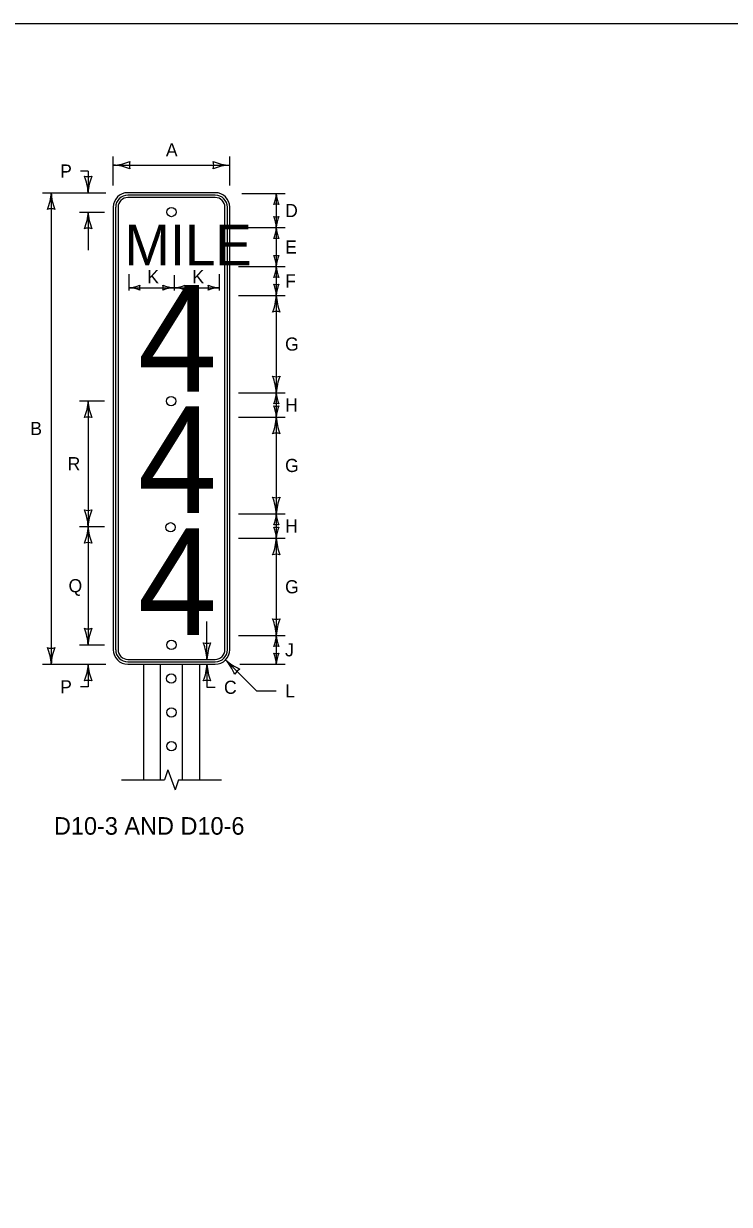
# Model space of a CAD drawing. Extents: x 49991.4 to 50021, y 49987.6 to 50011.4.
# Drawn here: x 50008.65 to 50011.87, y 49993.61 to 49999 of the extents above; entities that cross this region are included whole.
import ezdxf

# ---------------------------------------------------------------- set-up
doc = ezdxf.new("R2010")
doc.units = 0
for name, color, linetype in [('Level 1', 7, 'Continuous'), ('Level 2', 7, 'Continuous'), ('Level 3', 7, 'Continuous'), ('Level 6', 7, 'Continuous')]:
    doc.layers.add(name, color=color, linetype=linetype)

msp = doc.modelspace()

# ---------------------------------------------------------------- linework, layer by layer
at = {"layer": 'Level 1'}
for p, q in [((50009.5245, 49998.2278), (50009.1261, 49998.2278)), ((50009.5246, 49998.2167), (50009.1261, 49998.2167)), ((50009.5246, 49998.2057), (50009.1261, 49998.2057)), ((50009.0597, 49998.1614), (50009.0597, 49996.1429)), ((50009.0707, 49998.1614), (50009.0707, 49996.143)), ((50009.0818, 49998.1615), (50009.0818, 49996.1429)), ((50009.5688, 49996.1429), (50009.5688, 49998.1615)), ((50009.5799, 49996.143), (50009.5799, 49998.1614)), ((50009.5909, 49996.1429), (50009.5909, 49998.1614)), ((50009.1261, 49996.0986), (50009.5246, 49996.0986)), ((50009.1261, 49996.0876), (50009.5246, 49996.0876)), ((50009.1261, 49996.0765), (50009.5245, 49996.0765)), ((50009.1975, 49996.0765), (50009.1975, 49995.5489)), ((50009.2732, 49996.0765), (50009.2732, 49995.5489)), ((50009.3737, 49996.0765), (50009.3737, 49995.5489)), ((50009.4529, 49996.0765), (50009.4529, 49995.5489))]:
    msp.add_line(p, q, dxfattribs=at)
msp.add_lwpolyline([(49999.3835, 49998.9992), (50016.7501, 49998.9992), (50016.7501, 49987.7988), (49999.3835, 49987.7988)], close=True, dxfattribs=at)
for centre in [(50009.3252, 49998.1397), (50009.3232, 49997.2773), (50009.321, 49996.7012), (50009.3252, 49996.1646), (50009.324, 49996.0109), (50009.3252, 49995.8567), (50009.3252, 49995.7028)]:
    msp.add_circle(centre, 0.0213, dxfattribs=at)
for centre, radius, start, end in [((50009.1261, 49998.1614), 0.0664, 90, 180), ((50009.1261, 49998.1614), 0.0553, 90, 180), ((50009.1261, 49998.1615), 0.0443, 90, 180), ((50009.5245, 49998.1614), 0.0664, 0, 90), ((50009.5246, 49998.1614), 0.0553, 0, 90), ((50009.5246, 49998.1615), 0.0443, 0, 90), ((50009.1261, 49996.1429), 0.0664, 180, 270), ((50009.1261, 49996.143), 0.0553, 180, 270), ((50009.1261, 49996.1429), 0.0443, 180, 270), ((50009.5245, 49996.1429), 0.0664, 270, 360), ((50009.5246, 49996.143), 0.0553, 270, 360), ((50009.5246, 49996.1429), 0.0443, 270, 360)]:
    msp.add_arc(centre, radius, start, end, dxfattribs=at)
at = {"layer": 'Level 3'}
for p, q in [((50009.0597, 49998.2614), (50009.0597, 49998.3933)), ((50009.0597, 49998.3533), (50009.5909, 49998.3533)), ((50009.5909, 49998.2614), (50009.5909, 49998.3933)), ((50008.9453, 49998.3265), (50008.9111, 49998.3265)), ((50008.9453, 49998.3265), (50008.9453, 49998.2277)), ((50008.7369, 49998.2277), (50009.0261, 49998.2277)), ((50008.7769, 49998.2277), (50008.7769, 49996.0765)), ((50009.6464, 49998.2241), (50009.843, 49998.2241)), ((50009.803, 49998.2241), (50009.803, 49998.0689)), ((50008.9053, 49998.1397), (50009.0197, 49998.1397)), ((50008.9453, 49998.1397), (50008.9453, 49997.9663)), ((50009.6309, 49998.0689), (50009.843, 49998.0689)), ((50009.803, 49998.0689), (50009.803, 49997.8912)), ((50009.6309, 49997.8912), (50009.843, 49997.8912)), ((50009.803, 49997.8912), (50009.803, 49997.7593)), ((50009.1307, 49997.8558), (50009.1307, 49997.782)), ((50009.1307, 49997.8539), (50009.1307, 49997.782)), ((50009.1307, 49997.8521), (50009.1307, 49997.782)), ((50009.3368, 49997.8521), (50009.3368, 49997.782)), ((50009.5428, 49997.8558), (50009.5428, 49997.782)), ((50009.5428, 49997.8539), (50009.5428, 49997.782)), ((50009.5428, 49997.8521), (50009.5428, 49997.782)), ((50009.1307, 49997.7945), (50009.3538, 49997.7945)), ((50009.1307, 49997.7945), (50009.3538, 49997.7945)), ((50009.1307, 49997.7945), (50009.3538, 49997.7945)), ((50009.3538, 49997.7945), (50009.5428, 49997.7945)), ((50009.3538, 49997.7945), (50009.5428, 49997.7945)), ((50009.3538, 49997.7945), (50009.5428, 49997.7945)), ((50009.6309, 49997.7593), (50009.843, 49997.7593)), ((50009.803, 49997.7593), (50009.803, 49997.315)), ((50008.9053, 49997.2779), (50009.0197, 49997.2779)), ((50008.9453, 49997.2779), (50008.9453, 49996.705)), ((50009.6309, 49997.315), (50009.843, 49997.315)), ((50009.803, 49997.315), (50009.803, 49997.2042)), ((50009.6309, 49997.2042), (50009.843, 49997.2042)), ((50009.803, 49997.2042), (50009.803, 49996.7626)), ((50009.6309, 49996.7626), (50009.843, 49996.7626)), ((50009.803, 49996.7626), (50009.803, 49996.6518)), ((50008.9053, 49996.705), (50009.0197, 49996.705)), ((50008.9453, 49996.705), (50008.9453, 49996.1646)), ((50009.6309, 49996.6518), (50009.843, 49996.6518)), ((50009.803, 49996.6518), (50009.803, 49996.2082)), ((50009.4869, 49996.0986), (50009.4867, 49996.2721)), ((50009.6309, 49996.2082), (50009.843, 49996.2082)), ((50009.6309, 49996.2082), (50009.843, 49996.2082)), ((50009.803, 49996.2082), (50009.803, 49996.0765)), ((50008.9053, 49996.1646), (50009.0197, 49996.1646)), ((50009.5718, 49996.0963), (50009.7131, 49995.955)), ((50008.7369, 49996.0765), (50009.0261, 49996.0765)), ((50008.9453, 49996.0765), (50008.9453, 49995.9736)), ((50009.4869, 49996.0765), (50009.4869, 49995.9715)), ((50009.637, 49996.0765), (50009.843, 49996.0765)), ((50008.9453, 49995.9736), (50008.9111, 49995.9736)), ((50009.4869, 49995.9715), (50009.5245, 49995.9715)), ((50009.7131, 49995.955), (50009.803, 49995.955))]:
    msp.add_line(p, q, dxfattribs=at)
for centre, radius, start, end in [((50009.0482, 49998.586), 0.233, 272.8273, 292.0772), ((50009.0506, 49998.1312), 0.2223, 67.456, 87.6395), ((50009.1879, 49998.3533), 0.0548, 162.1388, 197.8612), ((50009.6001, 49998.5755), 0.2223, 247.456, 267.6395), ((50009.4627, 49998.3533), 0.0548, 342.1388, 17.8612), ((50009.6024, 49998.1206), 0.233, 92.8273, 112.0772), ((50008.9453, 49998.3559), 0.0548, 252.1388, 287.8612), ((50008.7126, 49998.2162), 0.233, 2.8273, 22.0772), ((50009.1675, 49998.2186), 0.2223, 157.456, 177.6395), ((50008.5548, 49998.2369), 0.2223, 337.456, 357.6395), ((50009.0096, 49998.2392), 0.233, 182.8273, 202.0772), ((50009.6549, 49998.2302), 0.1482, 337.456, 357.6395), ((50009.9582, 49998.2318), 0.1553, 182.8273, 202.0772), ((50008.7769, 49998.0995), 0.0548, 72.1388, 107.8612), ((50008.7232, 49998.1489), 0.2223, 337.456, 357.6395), ((50009.178, 49998.1512), 0.233, 182.8273, 202.0772), ((50009.803, 49998.1387), 0.0365, 72.1388, 107.8612), ((50009.803, 49998.1544), 0.0365, 252.1388, 287.8612), ((50009.6479, 49998.0613), 0.1553, 2.8273, 22.0772), ((50009.9511, 49998.0628), 0.1482, 157.456, 177.6395), ((50008.9453, 49998.0115), 0.0548, 72.1388, 107.8612), ((50009.6549, 49998.075), 0.1482, 337.456, 357.6395), ((50009.9582, 49998.0766), 0.1553, 182.8273, 202.0772), ((50009.803, 49997.9835), 0.0365, 72.1388, 107.8612), ((50009.803, 49997.9767), 0.0365, 252.1388, 287.8612), ((50009.6479, 49997.8836), 0.1553, 2.8273, 22.0772), ((50009.9511, 49997.8851), 0.1482, 157.456, 177.6395), ((50009.6549, 49997.8973), 0.1482, 337.456, 357.6395), ((50009.9582, 49997.8989), 0.1553, 182.8273, 202.0772), ((50009.803, 49997.8058), 0.0365, 72.1388, 107.8612), ((50009.1231, 49997.9497), 0.1553, 272.8273, 292.0772), ((50009.1231, 49997.9497), 0.1553, 272.8273, 292.0772), ((50009.1231, 49997.9497), 0.1553, 272.8273, 292.0772), ((50009.1246, 49997.6464), 0.1482, 67.456, 87.6395), ((50009.1246, 49997.6464), 0.1482, 67.456, 87.6395), ((50009.1246, 49997.6464), 0.1482, 67.456, 87.6395), ((50009.2162, 49997.7945), 0.0365, 162.1388, 197.8612), ((50009.2162, 49997.7945), 0.0365, 162.1388, 197.8612), ((50009.2162, 49997.7945), 0.0365, 162.1388, 197.8612), ((50009.3429, 49997.9426), 0.1482, 247.456, 267.6395), ((50009.2513, 49997.7945), 0.0365, 342.1388, 17.8612), ((50009.3444, 49997.6394), 0.1553, 92.8273, 112.0772), ((50009.3291, 49997.9497), 0.1553, 272.8273, 292.0772), ((50009.3307, 49997.6464), 0.1482, 67.456, 87.6395), ((50009.4223, 49997.7945), 0.0365, 162.1388, 197.8612), ((50009.5489, 49997.9426), 0.1482, 247.456, 267.6395), ((50009.4573, 49997.7945), 0.0365, 342.1388, 17.8612), ((50009.5489, 49997.9426), 0.1482, 247.456, 267.6395), ((50009.4573, 49997.7945), 0.0365, 342.1388, 17.8612), ((50009.5489, 49997.9426), 0.1482, 247.456, 267.6395), ((50009.4573, 49997.7945), 0.0365, 342.1388, 17.8612), ((50009.5505, 49997.6394), 0.1553, 92.8273, 112.0772), ((50009.5505, 49997.6394), 0.1553, 92.8273, 112.0772), ((50009.5505, 49997.6394), 0.1553, 92.8273, 112.0772), ((50009.5809, 49997.7685), 0.2223, 337.456, 357.6395), ((50009.803, 49997.8448), 0.0365, 252.1388, 287.8612), ((50009.6479, 49997.7517), 0.1553, 2.8273, 22.0772), ((50009.9511, 49997.7532), 0.1482, 157.456, 177.6395), ((50010.0357, 49997.7708), 0.233, 182.8273, 202.0772), ((50009.803, 49997.6311), 0.0548, 72.1388, 107.8612), ((50009.803, 49997.4432), 0.0548, 252.1388, 287.8612), ((50009.5703, 49997.3035), 0.233, 2.8273, 22.0772), ((50010.0252, 49997.3059), 0.2223, 157.456, 177.6395), ((50008.7232, 49997.2871), 0.2223, 337.456, 357.6395), ((50009.178, 49997.2894), 0.233, 182.8273, 202.0772), ((50009.6549, 49997.3211), 0.1482, 337.456, 357.6395), ((50009.9582, 49997.3227), 0.1553, 182.8273, 202.0772), ((50009.803, 49997.2296), 0.0365, 72.1388, 107.8612), ((50009.803, 49997.2897), 0.0365, 252.1388, 287.8612), ((50009.6479, 49997.1966), 0.1553, 2.8273, 22.0772), ((50009.9511, 49997.1981), 0.1482, 157.456, 177.6395), ((50008.9453, 49997.1497), 0.0548, 72.1388, 107.8612), ((50009.5809, 49997.2134), 0.2223, 337.456, 357.6395), ((50010.0357, 49997.2157), 0.233, 182.8273, 202.0772), ((50009.803, 49997.076), 0.0548, 72.1388, 107.8612), ((50009.803, 49996.8908), 0.0548, 252.1388, 287.8612), ((50009.5703, 49996.7511), 0.233, 2.8273, 22.0772), ((50010.0252, 49996.7535), 0.2223, 157.456, 177.6395), ((50008.9453, 49996.8332), 0.0548, 252.1388, 287.8612), ((50008.7126, 49996.6935), 0.233, 2.8273, 22.0772), ((50009.1675, 49996.6959), 0.2223, 157.456, 177.6395), ((50009.6549, 49996.7687), 0.1482, 337.456, 357.6395), ((50009.9582, 49996.7703), 0.1553, 182.8273, 202.0772), ((50008.7232, 49996.7142), 0.2223, 337.456, 357.6395), ((50009.178, 49996.7165), 0.233, 182.8273, 202.0772), ((50009.803, 49996.6772), 0.0365, 72.1388, 107.8612), ((50009.803, 49996.7373), 0.0365, 252.1388, 287.8612), ((50009.6479, 49996.6442), 0.1553, 2.8273, 22.0772), ((50009.9511, 49996.6457), 0.1482, 157.456, 177.6395), ((50008.9453, 49996.5768), 0.0548, 72.1388, 107.8612), ((50009.5809, 49996.661), 0.2223, 337.456, 357.6395), ((50010.0357, 49996.6633), 0.233, 182.8273, 202.0772), ((50009.803, 49996.5236), 0.0548, 72.1388, 107.8612), ((50009.803, 49996.3364), 0.0548, 252.1388, 287.8612), ((50009.5703, 49996.1967), 0.233, 2.8273, 22.0772), ((50010.0252, 49996.1991), 0.2223, 157.456, 177.6395), ((50008.9453, 49996.2928), 0.0548, 252.1388, 287.8612), ((50008.7126, 49996.1531), 0.233, 2.8273, 22.0772), ((50009.1675, 49996.1555), 0.2223, 157.456, 177.6395), ((50009.6549, 49996.2143), 0.1482, 337.456, 357.6395), ((50009.9582, 49996.2159), 0.1553, 182.8273, 202.0772), ((50008.7769, 49996.2047), 0.0548, 252.1388, 287.8612), ((50008.5442, 49996.065), 0.233, 2.8273, 22.0772), ((50008.9991, 49996.0674), 0.2223, 157.456, 177.6395), ((50009.4869, 49996.2268), 0.0548, 252.1388, 287.8612), ((50009.2542, 49996.0871), 0.233, 2.8273, 22.0772), ((50009.7091, 49996.0895), 0.2223, 157.456, 177.6395), ((50009.803, 49996.1228), 0.0365, 72.1388, 107.8612), ((50009.4083, 49995.9457), 0.2223, 22.456, 42.6395), ((50009.7282, 49996.269), 0.233, 227.8273, 247.0772), ((50009.803, 49996.162), 0.0365, 252.1388, 287.8612), ((50009.6479, 49996.0689), 0.1553, 2.8273, 22.0772), ((50009.9511, 49996.0704), 0.1482, 157.456, 177.6395), ((50008.7232, 49996.0857), 0.2223, 337.456, 357.6395), ((50009.178, 49996.088), 0.233, 182.8273, 202.0772), ((50009.2648, 49996.0857), 0.2223, 337.456, 357.6395), ((50009.7196, 49996.088), 0.233, 182.8273, 202.0772), ((50009.6625, 49996.0057), 0.0548, 117.1388, 152.8612), ((50008.9453, 49995.9483), 0.0548, 72.1388, 107.8612), ((50009.4869, 49995.9483), 0.0548, 72.1388, 107.8612)]:
    msp.add_arc(centre, radius, start, end, dxfattribs=at)
at = {"layer": 'Level 6'}
for p, q in [((50009.0975, 49995.5489), (50009.2928, 49995.5489)), ((50009.309, 49995.5946), (50009.2928, 49995.5489)), ((50009.309, 49995.5946), (50009.3252, 49995.5489)), ((50009.3252, 49995.5489), (50009.3414, 49995.5032)), ((50009.3576, 49995.5489), (50009.3414, 49995.5032)), ((50009.3576, 49995.5489), (50009.5529, 49995.5489))]:
    msp.add_line(p, q, dxfattribs=at)

# ---------------------------------------------------------------- texts
at = {"layer": 'Level 1'}
for s, height, p in [('MILE', 0.1859, (50009.1107, 49997.8958)), ('4', 0.4869, (50009.171, 49997.3203)), ('4', 0.4869, (50009.171, 49996.7669)), ('4', 0.4869, (50009.171, 49996.2093))]:
    msp.add_text(s, height=height, dxfattribs=at).set_placement(p)
at = {"layer": 'Level 2'}
for s, height, p in [('A', 0.06, (50009.2996, 49998.3933)), ('P', 0.06, (50008.8175, 49998.2965)), ('D', 0.06, (50009.843, 49998.1165)), ('E', 0.06, (50009.843, 49997.95)), ('K', 0.06, (50009.2142, 49997.8145)), ('K', 0.06, (50009.4203, 49997.8145)), ('F', 0.06, (50009.843, 49997.7952)), ('G', 0.06, (50009.843, 49997.5072)), ('H', 0.06, (50009.843, 49997.2296)), ('B', 0.06, (50008.6814, 49997.1221)), ('R', 0.06, (50008.8516, 49996.9614)), ('G', 0.06, (50009.843, 49996.9534)), ('H', 0.06, (50009.843, 49996.6772)), ('Q', 0.06, (50008.8559, 49996.4048)), ('G', 0.06, (50009.843, 49996.4)), ('J', 0.06, (50009.843, 49996.1124)), ('P', 0.06, (50008.8175, 49995.9436)), ('C', 0.06, (50009.5645, 49995.9415)), ('L', 0.06, (50009.843, 49995.925)), ('D10-3 AND D10-6', 0.08, (50008.7896, 49995.2989))]:
    msp.add_text(s, height=height, dxfattribs=at).set_placement(p)

doc.saveas('drawing.dxf')
